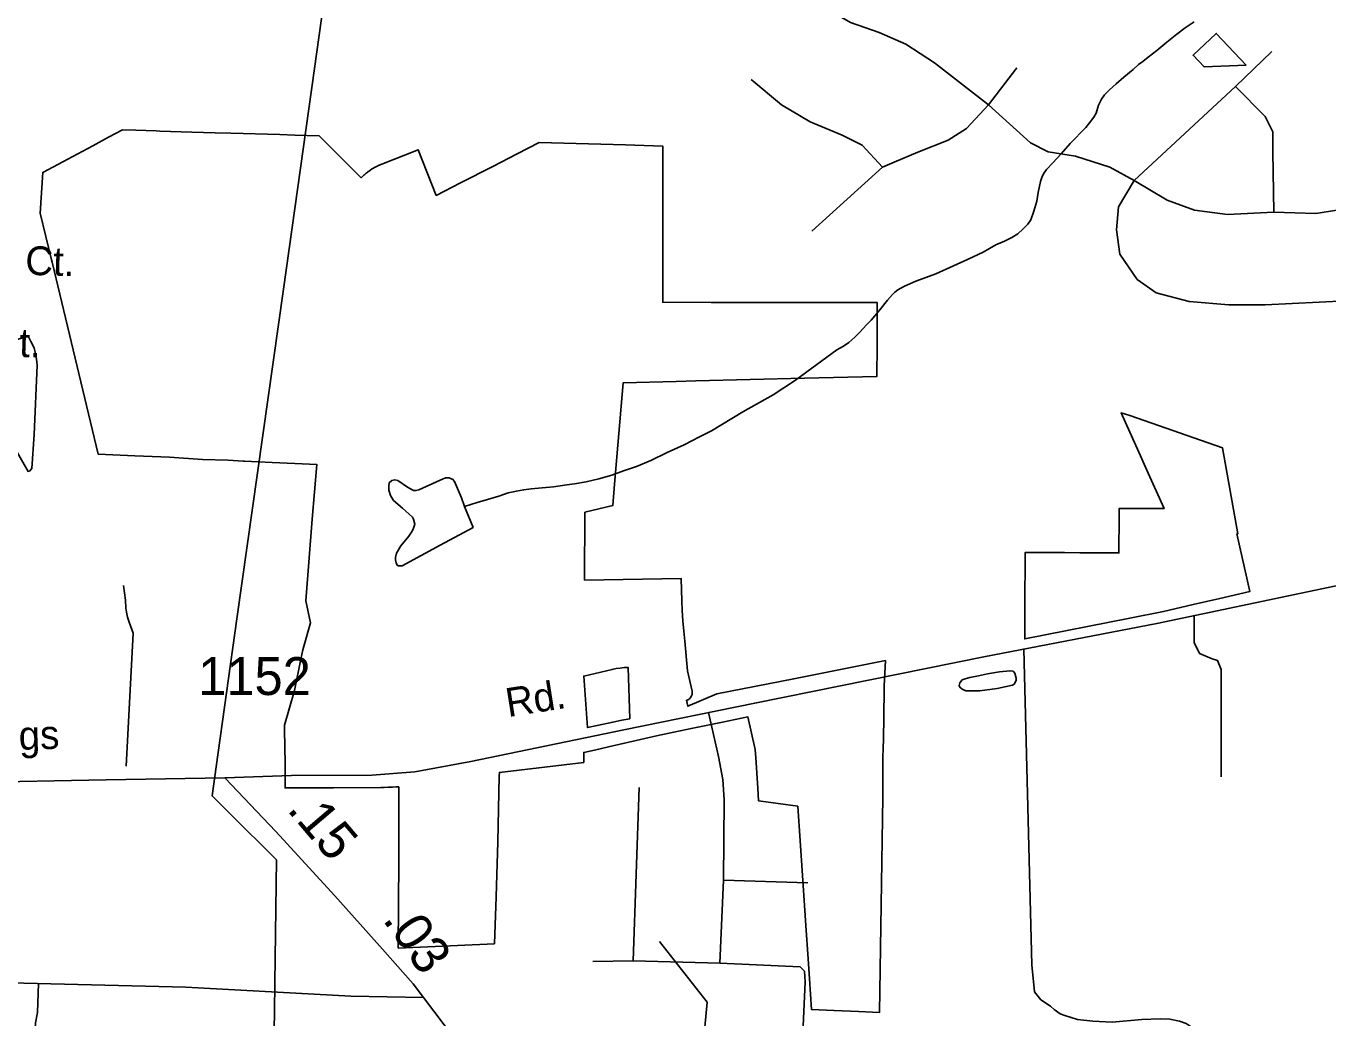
# Model space of a CAD drawing. Extents: x 2001466 to 2224147, y 644118 to 847247.
# Drawn here: x 2051357 to 2055654, y 692499 to 695772 of the extents above; entities that cross this region are included whole.
import ezdxf

# ---------------------------------------------------------------- set-up
doc = ezdxf.new("R2010")
doc.units = 0
for name, color, linetype in [('Exist Boundary Political City Limit New', 7, 'Continuous'), ('Exist Boundary Political City Limit New Hole', 7, 'Continuous'), ('Exist Hydrographic Misc Water Feature', 7, 'Continuous'), ('Exist Road Non-System Type 51', 7, 'Continuous'), ('Exist Road Non-System Type 51 Label', 7, 'Continuous'), ('Exist Road Secondary Mileage Hundredths English Label', 7, 'Continuous'), ('Exist Road Secondary Type 51 Attributed', 7, 'Continuous'), ('Exist Road Secondary Type 51 Label', 7, 'Continuous'), ('Exist Road Secondary Type 51 Number Label', 7, 'Continuous'), ('Exist Utilities Electrical Transmission Line', 7, 'Continuous'), ('Map Preparation Boundary City Limit Buffer Line', 7, 'Continuous')]:
    doc.layers.add(name, color=color, linetype=linetype)

msp = doc.modelspace()

# ---------------------------------------------------------------- linework, layer by layer
at = {"layer": 'Exist Boundary Political City Limit New'}
msp.add_lwpolyline([(2053241.5, 693463.6), (2053209.5, 693457), (2053197.6, 693626.5), (2053291.2, 693648.4), (2053304.2, 693651.2), (2053317.4, 693653.2), (2053330.6, 693654.7), (2053343.9, 693655.5), (2053349.2, 693486.1), (2053323.4, 693480.8), (2053293.8, 693474.5), (2053241.5, 693463.6)], dxfattribs=at)
at = {"layer": 'Exist Boundary Political City Limit New Hole'}
for points in [[(2055384.4, 695642.4), (2055285.2, 695747.4), (2055208.9, 695675.4), (2055245.2, 695636.8), (2055384.4, 695642.4)], [(2053335.5, 695380.2), (2053050.8, 695387.8), (2052978, 695350.4), (2052897.1, 695308.7), (2052790.9, 695253.9), (2052710.4, 695212.5), (2052650.6, 695363.5), (2052530.8, 695316), (2052529.4, 695315.5), (2052527.5, 695314.6), (2052525.8, 695313.9), (2052523.9, 695313.1), (2052522.1, 695312.3), (2052520.2, 695311.4), (2052518.4, 695310.5), (2052517, 695309.9), (2052515.8, 695309.2), (2052514.2, 695308.6), (2052513, 695308), (2052511.2, 695307), (2052509.9, 695306.2), (2052508.6, 695305.6), (2052506.8, 695304.6), (2052505.1, 695303.7), (2052503.4, 695302.6), (2052501.8, 695301.6), (2052499.2, 695300.1), (2052497.4, 695298.9), (2052495.8, 695297.9), (2052494, 695296.8), (2052492.1, 695295.5), (2052490, 695294), (2052488.8, 695293.1), (2052487.5, 695292.3), (2052485.9, 695291.1), (2052484.2, 695289.9), (2052482.8, 695288.6), (2052481, 695287.4), (2052479.5, 695286.2), (2052477.9, 695285), (2052476.8, 695284), (2052475.8, 695283), (2052474.5, 695282.1), (2052473.2, 695281.1), (2052471.8, 695279.7), (2052470.8, 695278.8), (2052469.8, 695277.8), (2052468.5, 695276.7), (2052467.4, 695275.7), (2052466, 695274.4), (2052464.5, 695273), (2052462.8, 695271.1), (2052426.6, 695307.1), (2052323.9, 695409.4), (2052244.2, 695411.8), (2052193.8, 695413.3), (2052032.5, 695418.1), (2051981.1, 695419.6), (2051904, 695421.9), (2051798.5, 695425.1), (2051786.4, 695425.4), (2051718.5, 695427.9), (2051675.5, 695429.5), (2051628.8, 695404.5), (2051576.8, 695376.7), (2051411.6, 695288.5), (2051403.5, 695154), (2051441.1, 695000), (2051442.9, 694992.8), (2051595.1, 694359.4), (2051715.4, 694353.2), (2051829.9, 694348.9), (2051939.6, 694341.7), (2052023.4, 694338.9), (2052073.5, 694336.1), (2052077.6, 694335.9), (2052169.4, 694331.4), (2052243.8, 694328.4), (2052316.5, 694324.8), (2052301.2, 694144.9), (2052279.8, 693874.6), (2052295.6, 693802.1), (2052269.8, 693712.8), (2052263.8, 693682.9), (2052242.8, 693578.6), (2052210.1, 693465.1), (2052211.1, 693377.9), (2052211.4, 693352.6), (2052211.8, 693325.2), (2052211.8, 693257.4), (2052371.8, 693258.2), (2052527.4, 693259.1), (2052538.9, 693259.2), (2052551.4, 693259.6), (2052566.4, 693260.1), (2052577.9, 693260.7), (2052586.8, 693261.2), (2052586.9, 693018.1), (2052585.1, 692729.1), (2052903, 692743.2)], [(2052903, 692743.2), (2052907.9, 692898), (2052913.9, 693080.2), (2052918.8, 693296.6), (2052919, 693309), (2053197.5, 693342), (2053197.6, 693374.9), (2053232.8, 693382.3), (2053279.1, 693393), (2053437.2, 693429.2), (2053474.2, 693437.7), (2053557.9, 693454.9), (2053655.5, 693474.9), (2053739.2, 693492.2), (2053763.2, 693384), (2053765, 693356.4), (2053771.8, 693256.6), (2053774.6, 693214.5), (2053904.1, 693197.2), (2053919.5, 692968.8), (2053922.9, 692918.7), (2053930.6, 692803.4), (2053938, 692693.4), (2053942.5, 692627.3), (2053949.2, 692526.7), (2054024.5, 692523.4), (2054104.1, 692519.9), (2054173.9, 692516.8), (2054184.9, 693227.4), (2054185.2, 693369.1), (2054185.5, 693378), (2054187.6, 693481.4), (2054188.8, 693594.8), (2054193, 693677.9), (2053890.6, 693617.9), (2053637.1, 693567.6), (2053541, 693527.2), (2053537, 693546.8), (2053539.1, 693547.5), (2053543.1, 693549.4), (2053546.8, 693551.9), (2053550.2, 693555.6), (2053553.6, 693561.1), (2053555.1, 693565.9), (2053555.6, 693570.3), (2053555.5, 693573.3), (2053554.9, 693576.8), (2053540.4, 693643.8), (2053531.1, 693741.4), (2053527.5, 693775.1), (2053524.6, 693808.9), (2053522.4, 693842.8), (2053520.8, 693876.6), (2053519.8, 693910.5), (2053519, 693948.9), (2053200.4, 693943.1), (2053201.6, 694167.2), (2053293.5, 694190), (2053299.5, 694259.8), (2053328, 694594.7), (2053502.8, 694599.1), (2053568, 694600.7), (2053925.8, 694609.6), (2054165.2, 694615.6), (2054165.9, 694718.7), (2054166.4, 694820.4), (2054166.4, 694859.2), (2054133.4, 694858.9), (2053944.4, 694859.1), (2053788.4, 694859.3), (2053669.4, 694859.6), (2053618.4, 694859.6), (2053458.4, 694860), (2053458.4, 694929.8), (2053458.4, 695000), (2053458.4, 695060.8), (2053458.4, 695165.8), (2053458.4, 695270.8), (2053458.4, 695375.8), (2053335.5, 695380.2)], [(2055060.9, 694296.2), (2055112.9, 694179.5), (2055050, 694179.8), (2055000, 694179.9), (2054964.9, 694180.1), (2054964.6, 694134.1), (2054964.2, 694054.1), (2054964.2, 694033.1), (2054834.9, 694033.9), (2054783.9, 694034.2), (2054654.2, 694034.4), (2054654, 693982.1), (2054653.6, 693902.1), (2054653.4, 693829.4), (2054653, 693749.4), (2055000, 693818.2), (2055111, 693840.2), (2055208.5, 693862.6), (2055297.2, 693882.9), (2055396, 693905.6), (2055353.5, 694095.9), (2055356.8, 694096.4), (2055305.6, 694379.9), (2055000, 694486.3), (2054971.2, 694495.3), (2055000, 694431.5), (2055035.1, 694353.2), (2055047.6, 694325.5), (2055060.9, 694296.2)]]:
    msp.add_lwpolyline(points, dxfattribs=at)
at = {"layer": 'Exist Hydrographic Misc Water Feature'}
for points in [[(2052803.5, 694186.8), (2052845.5, 694199.1), (2052879.5, 694208.9), (2052917.7, 694220.9), (2052947.8, 694231), (2052975.5, 694237.3), (2052999.7, 694241.4), (2053023.7, 694245), (2053059.8, 694247.3), (2053097.3, 694251.3), (2053141.8, 694257.6), (2053167.4, 694261.3), (2053205.6, 694267.8), (2053247.6, 694277.6), (2053289.7, 694289.9), (2053329.2, 694303.7), (2053371.7, 694318), (2053419, 694338), (2053473.2, 694364.3), (2053529.4, 694390.2), (2053579.2, 694416.3), (2053619.2, 694436.3), (2053723.1, 694498.7), (2053823, 694554.6), (2053896.8, 694603), (2053966.7, 694654.9), (2054032.6, 694702.9), (2054054.5, 694715), (2054072.7, 694727.2), (2054092.2, 694745.4), (2054108.4, 694761.2), (2054130.4, 694785.4), (2054146.2, 694801.2), (2054158.3, 694815.2), (2054174.5, 694835.1), (2054200.1, 694867.3), (2054216.1, 694885.6), (2054224.1, 694893.3), (2054233.9, 694901.6), (2054255.9, 694913.6), (2054293.8, 694929.4), (2054360, 694953.8), (2054417.8, 694979.9), (2054464, 695001.7), (2054515.7, 695025.9), (2054557.5, 695050), (2054585.8, 695061.9), (2054610, 695074.1), (2054629.9, 695086.1), (2054647.7, 695102.1), (2054663.7, 695118.3), (2054673.5, 695132.2), (2054683.4, 695160.3), (2054693.2, 695194.1), (2054697.1, 695222.3), (2054705.3, 695258.4), (2054709.2, 695272.4), (2054715.2, 695284.5), (2054725.2, 695298.4), (2054745.3, 695320.4), (2054773.4, 695350.3), (2054803.1, 695384.3), (2054854.8, 695436.5), (2054867.3, 695452.4), (2054880.9, 695470.7), (2054888.9, 695484.5), (2054896.8, 695510.4), (2054906.7, 695530.5), (2054916.7, 695544.8), (2054932.9, 695560.6), (2054954.9, 695580.7), (2054980.7, 695602.8), (2055010.7, 695628.7), (2055028.5, 695644.6), (2055042.6, 695655), (2055060.7, 695668.9), (2055088.6, 695691.1), (2055122.4, 695718.8), (2055154.6, 695745.2), (2055182.5, 695765.2), (2055212.2, 695785.1)], [(2051247.1, 694712), (2051174.9, 694687.6), (2051169.4, 694671.9), (2051171.5, 694653.7), (2051179.3, 694633.9), (2051283.6, 694442), (2051363.6, 694302.1), (2051367.9, 694302.3), (2051375.9, 694312), (2051383.5, 694424), (2051393.1, 694652.1), (2051391.3, 694672.3), (2051386.8, 694694.1), (2051383.1, 694710), (2051372.8, 694730.2), (2051363.2, 694747.9), (2051255.3, 694716), (2051247.1, 694712)], [(2052803.5, 694186.8), (2052793.6, 694214.6), (2052771.3, 694268.7), (2052765.5, 694274.9), (2052753.2, 694280.8), (2052741.5, 694280.9), (2052731.5, 694276.8), (2052723.5, 694272.7), (2052653.6, 694240.7), (2052643.5, 694238.6), (2052635.3, 694238.6), (2052615.6, 694250.5), (2052583.7, 694272.4), (2052573.8, 694274.3), (2052563.6, 694272.2), (2052555.6, 694264.5), (2052553.7, 694254.2), (2052553.7, 694240.5), (2052559.7, 694222.5), (2052569.7, 694206.4), (2052599.7, 694180.3), (2052631.8, 694150.7), (2052635.7, 694144.5), (2052640, 694128.4), (2052635.9, 694114.4), (2052631.6, 694104.5), (2052620.2, 694088.4), (2052593.9, 694056.3), (2052579.8, 694032.5), (2052576.1, 694018.4), (2052576.1, 694010.3), (2052578.3, 694000.7), (2052582, 693992.4), (2052585.9, 693990.6), (2052598.2, 693990.3), (2052723.9, 694058.9), (2052832, 694117.1), (2052803.5, 694186.8)], [(2054570.2, 693640.2), (2054604.4, 693644.3), (2054614.5, 693642.4), (2054620.6, 693636.2), (2054624.3, 693620.2), (2054624.7, 693612.5), (2054618.4, 693600.5), (2054612.2, 693596.5), (2054562.6, 693586.2), (2054504.4, 693578.4), (2054474.4, 693578.1), (2054458.2, 693578.1), (2054446.6, 693583.9), (2054438.6, 693590), (2054436.7, 693596), (2054438.6, 693604.2), (2054446.6, 693613.9), (2054456.6, 693618.1), (2054472.4, 693622.1), (2054500.7, 693628), (2054530.6, 693634), (2054570.2, 693640.2)], [(2053600.5, 692503.7), (2053605, 692550.7), (2053447.1, 692750.8)], [(2055633.4, 691114.4), (2055565.9, 691113.1), (2054725, 690897.3), (2054208.1, 690927.5), (2053858.1, 691187.3), (2053758, 691359.9), (2053716, 691626.5), (2053715.1, 691895.6), (2053606, 692035.6), (2053565, 692134.9), (2053600.5, 692503.7)]]:
    msp.add_lwpolyline(points, dxfattribs=at)
at = {"layer": 'Exist Road Non-System Type 51'}
for points in [[(2054000.1, 695828.1), (2054077.8, 695783.7), (2054172.2, 695750.4), (2054261, 695711.5), (2054355.4, 695650.4), (2054533, 695511.5)], [(2055348.3, 695571.7), (2055468.3, 695688.1)], [(2054533, 695511.5), (2054627.3, 695633.7)], [(2054183.3, 695306), (2054116.7, 695378.2), (2054050.1, 695411.6), (2053944.6, 695456), (2053850.3, 695511.5), (2053750.4, 695594.8)], [(2055013.8, 695262.5), (2055348.3, 695571.7)], [(2055348.3, 695571.7), (2055446.5, 695473.5), (2055471.9, 695422.6), (2055471.9, 695357.1), (2055475.6, 695157)], [(2054533, 695511.5), (2054460.8, 695433.8), (2054399.8, 695394.9), (2054299.9, 695356), (2054222.2, 695322.7), (2054183.3, 695306)], [(2054533, 695511.5), (2054672.1, 695386.2), (2054730.3, 695357.1), (2054821.1, 695342.5), (2054933.9, 695306.1), (2055013.8, 695262.5)], [(2056086.4, 695357.1), (2055741, 695186.1), (2055682.8, 695164.3), (2055613.7, 695153.3), (2055475.6, 695157)], [(2054183.3, 695306), (2053950.2, 695095)], [(2055013.8, 695262.5), (2054962.9, 695175.2), (2054955.7, 695098.8), (2054966.6, 695018.7), (2055024.7, 694935.1), (2055086.6, 694891.4), (2055195.6, 694862.3), (2055326.5, 694851.4), (2055446.5, 694851.4), (2055802.8, 694869.6), (2055893.7, 694898.7), (2056104.6, 694982.3), (2056235.4, 695051.5)], [(2055475.6, 695157), (2055322.9, 695149.7), (2055213.8, 695164.3), (2055122.9, 695197), (2055013.8, 695262.5)], [(2051677.8, 693925.3), (2051684.9, 693877.2), (2051686.3, 693851.1), (2051688, 693837.1), (2051691.7, 693821), (2051697.4, 693804.9), (2051710.6, 693768.6), (2051686.8, 693329.5)], [(2055301.4, 693294.6), (2055301.4, 693647.9), (2055289.5, 693677.6), (2055271.7, 693683.5), (2055230.1, 693701.4), (2055212.3, 693737), (2055212.3, 693826.5)], [(2054650.5, 693715.8), (2054676.9, 692673.7), (2054685.8, 692584.6), (2054706.6, 692557.9), (2054738.6, 692537.1), (2054750.3, 692526.9), (2054770.1, 692512.5), (2054785.9, 692506.2), (2054805.8, 692499.8), (2054827.7, 692493.3), (2054877.6, 692488.3), (2054941.5, 692485), (2055039.7, 692493), (2055099.7, 692495.8), (2055131.7, 692495.1), (2055163.6, 692488.5), (2055185.4, 692480), (2055199.2, 692471.8), (2055211, 692461.5), (2055230.6, 692443.1), (2055258.1, 692418.6), (2055361.8, 692304.4)], [(2053658.9, 692953.7), (2053661.3, 693218.3), (2053656.5, 693285), (2053642.2, 693361.3), (2053608.8, 693506.4)], [(2053380.2, 693258.8), (2053361.1, 692686.8)], [(2053647, 692679.6), (2053658.9, 692953.7)], [(2053658.9, 692953.7), (2053937.6, 692944.2)], [(2053361.1, 692686.8), (2053227.8, 692684.4)], [(2053361.1, 692686.8), (2053647, 692679.6)], [(2053647, 692679.6), (2053911.4, 692667.7), (2053925.7, 692653.4), (2053928, 692617.7), (2053916.1, 692350.5)], [(2051397.4, 692612.1), (2051394.8, 692516.6), (2051387.9, 692482.2), (2051386.2, 692444.4), (2051387.9, 692413.5), (2051405.1, 692358.5), (2051420.4, 692323.1)]]:
    msp.add_lwpolyline(points, dxfattribs=at)
at = {"layer": 'Exist Road Secondary Type 51 Attributed'}
for points in [[(2055890.5, 693968.8), (2055088.9, 693800.6), (2054517.7, 693690.1), (2053761.9, 693537.7), (2053329.5, 693449.2), (2052824.6, 693345), (2052640, 693311.1), (2052497.9, 693300), (2052232.8, 693298.4), (2052012.7, 693290.6)], [(2052012.7, 693290.6), (2051621.4, 693284.3), (2051163.8, 693275.6), (2050777.2, 693277.1), (2050180.8, 693292.1), (2049612.8, 693300), (2049231.7, 693300.7)], [(2052668.3, 692566.2), (2052634.4, 692611.2), (2052524, 692735.5), (2052375.6, 692901.3), (2052181.6, 693113.7), (2052012.7, 693290.6)], [(2052668.3, 692566.2), (2052428.5, 692571), (2051884.1, 692600.2), (2051305, 692614.4), (2050809.5, 692635.7), (2050372.5, 692654.7), (2050015.9, 692666.5), (2049506.2, 692671.2), (2049383.7, 692667.9)], [(2057671.9, 689435.8), (2057551.9, 689500.6), (2057342.1, 689604.8), (2057192.2, 689663.2), (2056983.9, 689724), (2056542.1, 689823.5), (2055933, 689942.7), (2055551.2, 690013.7), (2055282.9, 690075.3), (2055011.5, 690174), (2054790.6, 690270.3), (2054579.2, 690387.2), (2054143.7, 690672.2), (2053965.4, 690808), (2053848.6, 690901.1), (2053750.8, 691005.3), (2053676.6, 691103.2), (2053471.5, 691391.4), (2053272.7, 691686.7), (2052919.2, 692202.2), (2052770.9, 692431.2), (2052668.3, 692566.2)]]:
    msp.add_lwpolyline(points, dxfattribs=at)
at = {"layer": 'Exist Utilities Electrical Transmission Line'}
for p, q in [((2052052.9, 693815.5), (2051984.1, 693326.9)), ((2052177.7, 692614.9), (2052176.5, 692519.3)), ((2052176.5, 692518.6), (2052156.3, 690949.7)), ((2052176.5, 692519.3), (2052176.5, 692518.6))]:
    msp.add_line(p, q, dxfattribs=at)
for points in [[(2052670.2, 698200.4), (2052666.6, 698141.7), (2052640.9, 697981.6), (2052597.4, 697691.7), (2052308.7, 695631.5), (2052206, 694903.6), (2052052.9, 693815.5)], [(2051984.1, 693326.9), (2051970.7, 693231.5), (2052028.4, 693173.9)], [(2052028.4, 693173.9), (2052182.9, 693019.8), (2052177.7, 692614.9)]]:
    msp.add_lwpolyline(points, dxfattribs=at)
at = {"layer": 'Map Preparation Boundary City Limit Buffer Line'}
for points in [[(2055384.4, 695642.4), (2055285.2, 695747.4), (2055208.9, 695675.4), (2055245.2, 695636.8), (2055384.4, 695642.4)], [(2053335.5, 695380.2), (2053050.8, 695387.8), (2052978, 695350.4), (2052897.1, 695308.7), (2052790.9, 695253.9), (2052710.4, 695212.5), (2052650.6, 695363.5), (2052530.8, 695316), (2052529.4, 695315.5), (2052527.5, 695314.6), (2052525.8, 695313.9), (2052523.9, 695313.1), (2052522.1, 695312.3), (2052520.2, 695311.4), (2052518.4, 695310.5), (2052517, 695309.9), (2052515.8, 695309.2), (2052514.2, 695308.6), (2052513, 695308), (2052511.2, 695307), (2052509.9, 695306.2), (2052508.6, 695305.6), (2052506.8, 695304.6), (2052505.1, 695303.7), (2052503.4, 695302.6), (2052501.8, 695301.6), (2052499.2, 695300.1), (2052497.4, 695298.9), (2052495.8, 695297.9), (2052494, 695296.8), (2052492.1, 695295.5), (2052490, 695294), (2052488.8, 695293.1), (2052487.5, 695292.3), (2052485.9, 695291.1), (2052484.2, 695289.9), (2052482.8, 695288.6), (2052481, 695287.4), (2052479.5, 695286.2), (2052477.9, 695285), (2052476.8, 695284), (2052475.8, 695283), (2052474.5, 695282.1), (2052473.2, 695281.1), (2052471.8, 695279.7), (2052470.8, 695278.8), (2052469.8, 695277.8), (2052468.5, 695276.7), (2052467.4, 695275.7), (2052466, 695274.4), (2052464.5, 695273), (2052462.8, 695271.1), (2052426.6, 695307.1), (2052323.9, 695409.4), (2052244.2, 695411.8), (2052193.8, 695413.3), (2052032.5, 695418.1), (2051981.1, 695419.6), (2051904, 695421.9), (2051798.5, 695425.1), (2051786.4, 695425.4), (2051718.5, 695427.9), (2051675.5, 695429.5), (2051628.8, 695404.5), (2051576.8, 695376.7), (2051411.6, 695288.5), (2051403.5, 695154), (2051441.1, 695000), (2051442.9, 694992.8), (2051595.1, 694359.4), (2051715.4, 694353.2), (2051829.9, 694348.9), (2051939.6, 694341.7), (2052023.4, 694338.9), (2052073.5, 694336.1), (2052077.6, 694335.9), (2052169.4, 694331.4), (2052243.8, 694328.4), (2052316.5, 694324.8), (2052301.2, 694144.9), (2052279.8, 693874.6), (2052295.6, 693802.1), (2052269.8, 693712.8), (2052263.8, 693682.9), (2052242.8, 693578.6), (2052210.1, 693465.1), (2052211.1, 693377.9), (2052211.4, 693352.6), (2052211.8, 693325.2), (2052211.8, 693257.4), (2052371.8, 693258.2), (2052527.4, 693259.1), (2052538.9, 693259.2), (2052551.4, 693259.6), (2052566.4, 693260.1), (2052577.9, 693260.7), (2052586.8, 693261.2), (2052586.9, 693018.1), (2052585.1, 692729.1), (2052903, 692743.2)], [(2052903, 692743.2), (2052907.9, 692898), (2052913.9, 693080.2), (2052918.8, 693296.6), (2052919, 693309), (2053197.5, 693342), (2053197.6, 693374.9), (2053232.8, 693382.3), (2053279.1, 693393), (2053437.2, 693429.2), (2053474.2, 693437.7), (2053557.9, 693454.9), (2053655.5, 693474.9), (2053739.2, 693492.2), (2053763.2, 693384), (2053765, 693356.4), (2053771.8, 693256.6), (2053774.6, 693214.5), (2053904.1, 693197.2), (2053919.5, 692968.8), (2053922.9, 692918.7), (2053930.6, 692803.4), (2053938, 692693.4), (2053942.5, 692627.3), (2053949.2, 692526.7), (2054024.5, 692523.4), (2054104.1, 692519.9), (2054173.9, 692516.8), (2054184.9, 693227.4), (2054185.2, 693369.1), (2054185.5, 693378), (2054187.6, 693481.4), (2054188.8, 693594.8), (2054193, 693677.9), (2053890.6, 693617.9), (2053637.1, 693567.6), (2053541, 693527.2), (2053537, 693546.8), (2053539.1, 693547.5), (2053543.1, 693549.4), (2053546.8, 693551.9), (2053550.2, 693555.6), (2053553.6, 693561.1), (2053555.1, 693565.9), (2053555.6, 693570.3), (2053555.5, 693573.3), (2053554.9, 693576.8), (2053540.4, 693643.8), (2053531.1, 693741.4), (2053527.5, 693775.1), (2053524.6, 693808.9), (2053522.4, 693842.8), (2053520.8, 693876.6), (2053519.8, 693910.5), (2053519, 693948.9), (2053200.4, 693943.1), (2053201.6, 694167.2), (2053293.5, 694190), (2053299.5, 694259.8), (2053328, 694594.7), (2053502.8, 694599.1), (2053568, 694600.7), (2053925.8, 694609.6), (2054165.2, 694615.6), (2054165.9, 694718.7), (2054166.4, 694820.4), (2054166.4, 694859.2), (2054133.4, 694858.9), (2053944.4, 694859.1), (2053788.4, 694859.3), (2053669.4, 694859.6), (2053618.4, 694859.6), (2053458.4, 694860), (2053458.4, 694929.8), (2053458.4, 695000), (2053458.4, 695060.8), (2053458.4, 695165.8), (2053458.4, 695270.8), (2053458.4, 695375.8), (2053335.5, 695380.2)], [(2055060.9, 694296.2), (2055112.9, 694179.5), (2055050, 694179.8), (2055000, 694179.9), (2054964.9, 694180.1), (2054964.6, 694134.1), (2054964.2, 694054.1), (2054964.2, 694033.1), (2054834.9, 694033.9), (2054783.9, 694034.2), (2054654.2, 694034.4), (2054654, 693982.1), (2054653.6, 693902.1), (2054653.4, 693829.4), (2054653, 693749.4), (2055000, 693818.2), (2055111, 693840.2), (2055208.5, 693862.6), (2055297.2, 693882.9), (2055396, 693905.6), (2055353.5, 694095.9), (2055356.8, 694096.4), (2055305.6, 694379.9), (2055000, 694486.3), (2054971.2, 694495.3), (2055000, 694431.5), (2055035.1, 694353.2), (2055047.6, 694325.5), (2055060.9, 694296.2)], [(2053241.5, 693463.6), (2053209.5, 693457), (2053197.6, 693626.5), (2053291.2, 693648.4), (2053304.2, 693651.2), (2053317.4, 693653.2), (2053330.6, 693654.7), (2053343.9, 693655.5), (2053349.2, 693486.1), (2053323.4, 693480.8), (2053293.8, 693474.5), (2053241.5, 693463.6)]]:
    msp.add_lwpolyline(points, dxfattribs=at)

# ---------------------------------------------------------------- texts
at = {"layer": 'Exist Road Non-System Type 51 Label'}
for s, p in [('Barbadous Ct.', (2050703.5, 694971.4)), ('St. Lucia Ct.', (2050712.3, 694699.2))]:
    msp.add_text(s, height=95, rotation=358.2081, dxfattribs=at).set_placement(p)
at = {"layer": 'Exist Road Secondary Mileage Hundredths English Label'}
for s, rotation, p in [('.15', 310.4012, (2052215.3, 693185.1)), ('.03', 305.3234, (2052531.5, 692822.9))]:
    msp.add_text(s, height=125, rotation=rotation, dxfattribs=at).set_placement(p)
at = {"layer": 'Exist Road Secondary Type 51 Label'}
for s, rotation, p in [('Rd.', 8.9725, (2052947.6, 693491.2)), ('Springs', 2.1176, (2051037.5, 693371.4))]:
    msp.add_text(s, height=95, rotation=rotation, dxfattribs=at).set_placement(p)
at = {"layer": 'Exist Road Secondary Type 51 Number Label'}
msp.add_text('1152', height=125, dxfattribs=at).set_placement((2051924.8, 693564.2))

doc.saveas('drawing.dxf')
